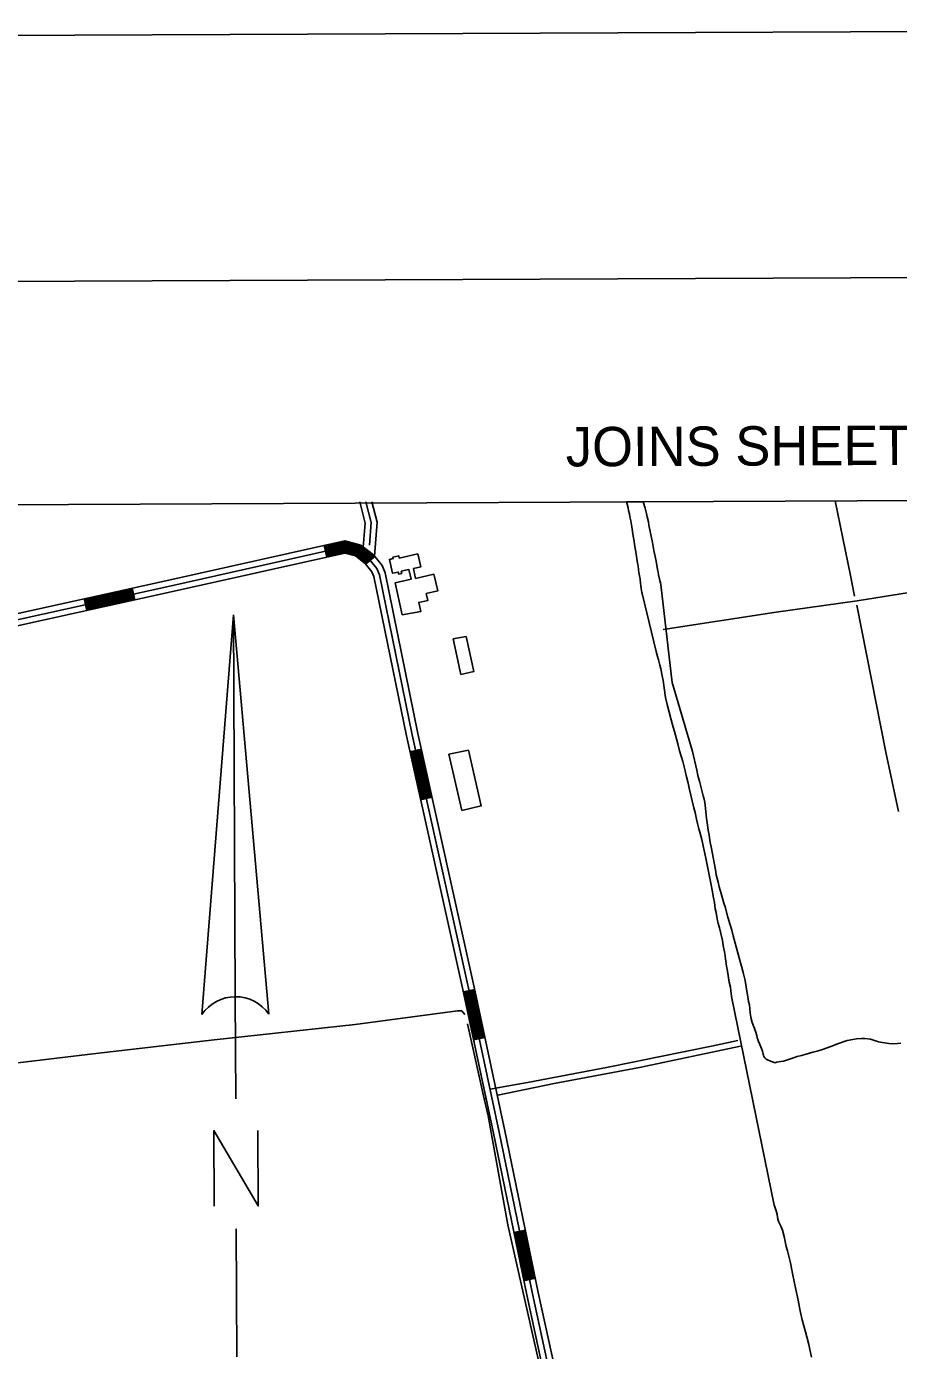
# Model space of a CAD drawing. Extents: x 3424494 to 3462436, y 522220 to 547718.
# Drawn here: x 3456706 to 3458923, y 543771 to 547135 of the extents above; entities that cross this region are included whole.
import ezdxf

# ---------------------------------------------------------------- set-up
doc = ezdxf.new("R2010")
doc.units = 0
for name, color, linetype in [('G-ANNO-NPLT', 7, 'Continuous'), ('V-ANNO-SYMB', 7, 'Continuous'), ('V-ANNO-TEXT', 7, 'Continuous'), ('V-BLDG-OTLN', 7, 'Continuous'), ('V-DTCH-CNTR', 7, 'Continuous'), ('V-GRID-FRAM', 7, 'Continuous'), ('V-ROAD-CNTR', 7, 'Continuous'), ('V-SITE-VEGE', 7, 'Continuous'), ('V-TOPO-SHOR', 7, 'Continuous')]:
    doc.layers.add(name, color=color, linetype=linetype)

msp = doc.modelspace()

# ---------------------------------------------------------------- linework, layer by layer
at = {"layer": 'G-ANNO-NPLT'}
msp.add_lwpolyline([(3425186.3, 522803.1), (3461852.6, 522968.4), (3461743.6, 547134.8), (3425077.3, 546969.5)], close=True, dxfattribs=at)
at = {"layer": 'V-ANNO-SYMB'}
for p, q in [((3457232.6, 545639.7), (3457152.2, 544624.3)), ((3457232.6, 545639.7), (3457322.2, 544625)), ((3457237, 544669.7), (3457232.6, 545639.7)), ((3457232.6, 545639.7), (3457322.2, 544625)), ((3457237, 544669.7), (3457232.6, 545639.7)), ((3457238.2, 544409.7), (3457237, 544669.7)), ((3457241.1, 543754.7), (3457239.6, 544079.7))]:
    msp.add_line(p, q, dxfattribs=at)
for points in [[(3427933.6, 523440.5), (3461016.5, 523589.7), (3460913.1, 546506), (3427830.3, 546356.9), (3427933.6, 523440.5)], [(3457183.4, 544137.4), (3457182.5, 544329.4), (3457295.4, 544137.9), (3457294.5, 544329.9)]]:
    msp.add_lwpolyline(points, dxfattribs=at)
for start, end in [(90.2583, 146.0529), (34.4638, 90.2583), (34.4638, 90.2472)]:
    msp.add_arc((3457237.4, 544566.9), 102.8, start, end, dxfattribs=at)
at = {"layer": 'V-BLDG-OTLN'}
for points in [[(3457661.4, 545639.6), (3457643.1, 545721), (3457684, 545730.3), (3457678.4, 545754.9), (3457659, 545750.5), (3457660.2, 545745.2), (3457652.3, 545743.4), (3457651.1, 545748.7), (3457636.6, 545745.4), (3457628.6, 545780.8), (3457638.6, 545783.1), (3457637.8, 545786.7), (3457652.6, 545790.1), (3457653.9, 545784), (3457700.8, 545794.7), (3457708.3, 545761.5), (3457689.8, 545757.3), (3457695.4, 545732.5), (3457742, 545743), (3457751.6, 545700.5), (3457722.5, 545693.9), (3457726.4, 545676.7), (3457703.4, 545671.4), (3457708.7, 545648.4)], [(3457823.9, 545584.8), (3457843.1, 545495.7), (3457810.5, 545488.6), (3457791.2, 545578.5)], [(3457829.6, 545296.1), (3457862.3, 545154.3), (3457812.9, 545143), (3457780, 545285.8)]]:
    msp.add_lwpolyline(points, close=True, dxfattribs=at)
at = {"layer": 'V-DTCH-CNTR'}
for points in [[(3458324.4, 545602.4), (3458611.5, 545647), (3458817.3, 545675.8), (3459230, 545741.9), (3459321.7, 545756.6), (3459657.1, 545812.5), (3460000.9, 545861.5), (3460200.9, 545894.6)], [(3458514, 544558.1), (3458447.3, 544544), (3458380.6, 544530.2), (3458313.9, 544516.6), (3458247.1, 544503.3), (3458180.3, 544490.1), (3458113.4, 544477.1), (3458046.5, 544464.4), (3457979.5, 544451.8), (3457912.6, 544439.5), (3457885.6, 544434.6)]]:
    msp.add_lwpolyline(points, dxfattribs=at)
at = {"layer": 'V-GRID-FRAM'}
msp.add_lwpolyline([(3428547.8, 545793.2), (3460200.7, 545935.9)], dxfattribs=at)
at = {"layer": 'V-ROAD-CNTR'}
for p, q in [((3457462.8, 545815.9), (3457469.3, 545786.6)), ((3457591.5, 545787.9), (3457568.2, 545769)), ((3456852.7, 545680.4), (3456859.2, 545651.1)), ((3456974.8, 545707.3), (3456981.2, 545678)), ((3457710.1, 545298.5), (3457680.8, 545292)), ((3457737.2, 545176.5), (3457707.9, 545170)), ((3457845.5, 544688.2), (3457816.2, 544682)), ((3457871.7, 544566), (3457842.3, 544559.7)), ((3457974.4, 544076.6), (3457945.1, 544070.5)), ((3457999.7, 543954.1), (3457970.3, 543948.1))]:
    msp.add_line(p, q, dxfattribs=at)
for points in [[(3456408.7, 545919), (3456433.5, 545801.4), (3456459.9, 545662.7), (3456474.1, 545632.8), (3456495.3, 545610.6), (3456539, 545593.8), (3456582.2, 545590), (3457081.9, 545700.2), (3457515.1, 545796.8), (3457542.2, 545789.4), (3457567.1, 545770.4), (3457584.1, 545749.5), (3457589.3, 545737.4), (3457671.8, 545332.2), (3457815, 544687.7), (3457893.1, 544322.5), (3457977.8, 543911.9), (3458020.4, 543715.5)], [(3456423.4, 545922.1), (3456448.2, 545804.4), (3456474.3, 545667.3), (3456486.6, 545641.4), (3456503.9, 545623.4), (3456542.4, 545608.6), (3456581.3, 545605.1), (3457078.6, 545714.8), (3457515.5, 545812.3), (3457549, 545803.1), (3457577.6, 545781.3), (3457597.1, 545757.3), (3457603.7, 545741.9), (3457686.5, 545335.3), (3457829.6, 544690.9), (3457907.8, 544325.6), (3457992.4, 543915), (3458035.1, 543718.6)], [(3456438.1, 545925.2), (3456463, 545807.3), (3456488.7, 545672), (3456499.1, 545650), (3456512.4, 545636.2), (3456545.8, 545623.3), (3456580.3, 545620.3), (3457075.4, 545729.5), (3457515.8, 545827.7), (3457555.7, 545816.8), (3457588.1, 545792.1), (3457610, 545765.2), (3457618.1, 545746.4), (3457701.2, 545338.4), (3457844.3, 544694.1), (3457922.4, 544328.7), (3458007.1, 543918.1), (3458049.8, 543721.7)], [(3457553.3, 545927.2), (3457567.3, 545872.8), (3457562.3, 545811.8)], [(3457577.8, 545817.3), (3457582.5, 545874.1), (3457568.8, 545927.2)], [(3457584.3, 545927.3), (3457597.6, 545875.4), (3457590.5, 545789.2)], [(3457463.4, 545813), (3457515.8, 545824.6), (3457554.4, 545814.1), (3457586, 545790), (3457589.2, 545786)], [(3457464.1, 545810), (3457515.7, 545821.5), (3457553, 545811.3), (3457583.9, 545787.8), (3457586.9, 545784.1)], [(3457464.7, 545807.1), (3457515.6, 545818.4), (3457551.7, 545808.6), (3457581.8, 545785.6), (3457584.6, 545782.2)], [(3457465.4, 545804.2), (3457515.5, 545815.3), (3457550.3, 545805.9), (3457579.7, 545783.5), (3457582.2, 545780.4)], [(3457466.1, 545801.2), (3457515.5, 545812.3), (3457549, 545803.1), (3457577.6, 545781.3), (3457579.9, 545778.5)], [(3457466.7, 545798.3), (3457515.4, 545809.2), (3457547.6, 545800.4), (3457575.5, 545779.1), (3457577.6, 545776.6)], [(3457467.4, 545795.4), (3457515.3, 545806.1), (3457546.2, 545797.6), (3457573.4, 545777), (3457575.2, 545774.7)], [(3457468, 545792.5), (3457515.3, 545803), (3457544.9, 545794.9), (3457571.3, 545774.8), (3457572.9, 545772.8)], [(3457468.7, 545789.5), (3457515.2, 545799.9), (3457543.5, 545792.2), (3457569.2, 545772.6), (3457570.6, 545770.9)], [(3456853.3, 545677.4), (3456975.4, 545704.4)], [(3456854, 545674.5), (3456976.1, 545701.4)], [(3456854.6, 545671.6), (3456976.7, 545698.5)], [(3456855.3, 545668.7), (3456977.3, 545695.6)], [(3456855.9, 545665.7), (3456978, 545692.6)], [(3456856.6, 545662.8), (3456978.6, 545689.7)], [(3456857.2, 545659.9), (3456979.3, 545686.8)], [(3456857.9, 545656.9), (3456979.9, 545683.9)], [(3456858.5, 545654), (3456980.6, 545680.9)], [(3457683.7, 545292.6), (3457710.8, 545170.6)], [(3457686.6, 545293.3), (3457713.7, 545171.3)], [(3457689.6, 545293.9), (3457716.7, 545171.9)], [(3457692.5, 545294.6), (3457719.6, 545172.6)], [(3457695.4, 545295.2), (3457722.5, 545173.2)], [(3457698.3, 545295.9), (3457725.4, 545173.9)], [(3457701.3, 545296.5), (3457728.4, 545174.5)], [(3457704.2, 545297.2), (3457731.3, 545175.2)], [(3457707.1, 545297.8), (3457734.2, 545175.8)], [(3457819.1, 544682.6), (3457845.3, 544560.4)], [(3457822.1, 544683.2), (3457848.2, 544561)], [(3457825, 544683.8), (3457851.1, 544561.6)], [(3457827.9, 544684.5), (3457854.1, 544562.2)], [(3457830.9, 544685.1), (3457857, 544562.9)], [(3457833.8, 544685.7), (3457859.9, 544563.5)], [(3457836.7, 544686.3), (3457862.9, 544564.1)], [(3457839.7, 544687), (3457865.8, 544564.7)], [(3457842.6, 544687.6), (3457868.7, 544565.4)], [(3457948, 544071.1), (3457973.2, 543948.7)], [(3457950.9, 544071.7), (3457976.2, 543949.3)], [(3457953.9, 544072.3), (3457979.1, 543949.9)], [(3457956.8, 544072.9), (3457982.1, 543950.5)], [(3457959.8, 544073.5), (3457985, 543951.1)], [(3457962.7, 544074.1), (3457987.9, 543951.7)], [(3457965.6, 544074.7), (3457990.9, 543952.3)], [(3457968.6, 544075.4), (3457993.8, 543952.9)], [(3457971.5, 544076), (3457996.8, 543953.5)]]:
    msp.add_lwpolyline(points, dxfattribs=at)
at = {"layer": 'V-SITE-VEGE'}
for p, q in [((3458231.7, 545927), (3458273.9, 545927.2)), ((3458235.4, 545911.4), (3458231.7, 545927)), ((3458273.9, 545927.2), (3458278.5, 545911.3)), ((3458236.6, 545905.1), (3458235.4, 545911.4)), ((3458238.8, 545896.3), (3458236.6, 545905.1)), ((3458240.1, 545889.2), (3458238.8, 545896.3)), ((3458242.4, 545878.7), (3458240.1, 545889.2)), ((3458244.7, 545863.6), (3458242.4, 545878.7)), ((3458278.5, 545911.3), (3458281.8, 545897.5)), ((3458281.8, 545897.5), (3458284.1, 545888.5)), ((3458284.1, 545888.5), (3458286.9, 545876.1)), ((3458245.9, 545857.6), (3458244.7, 545863.6)), ((3458248.5, 545839.4), (3458245.9, 545857.6)), ((3458286.9, 545876.1), (3458288.4, 545867.8)), ((3458288.4, 545867.8), (3458297.5, 545823.3)), ((3458250.6, 545827), (3458248.5, 545839.4)), ((3458251.9, 545818.2), (3458250.6, 545827)), ((3458254.2, 545804.2), (3458251.9, 545818.2)), ((3458297.5, 545823.3), (3458301, 545803.2)), ((3458255, 545800), (3458254.2, 545804.2)), ((3458259.5, 545771.3), (3458255, 545800)), ((3458301, 545803.2), (3458302.7, 545795.5)), ((3458302.7, 545795.5), (3458306.6, 545776.2)), ((3458260.7, 545764.8), (3458259.5, 545771.3)), ((3458262.2, 545754.6), (3458260.7, 545764.8)), ((3458262.9, 545747.7), (3458262.2, 545754.6)), ((3458265.8, 545730.7), (3458262.9, 545747.7)), ((3458306.6, 545776.2), (3458310.2, 545755.5)), ((3458310.2, 545755.5), (3458311.8, 545748.1)), ((3458311.8, 545748.1), (3458312.7, 545741.7)), ((3458267.1, 545719.8), (3458265.8, 545730.7)), ((3458267.4, 545714.2), (3458267.1, 545719.8)), ((3458269, 545707.1), (3458267.4, 545714.2)), ((3458312.7, 545741.7), (3458316.5, 545727.2)), ((3458316.5, 545727.2), (3458317.8, 545721.5)), ((3458317.8, 545721.5), (3458318.6, 545716.9)), ((3458318.6, 545716.9), (3458345.1, 545488.9)), ((3458270.7, 545696.4), (3458269, 545707.1)), ((3458271.3, 545694.3), (3458270.7, 545696.4)), ((3458307.1, 545546.4), (3458271.3, 545694.3)), ((3458310.3, 545534.1), (3458307.1, 545546.4)), ((3458312.4, 545525.5), (3458310.3, 545534.1)), ((3458316.1, 545512.4), (3458312.4, 545525.5)), ((3458318.5, 545502.3), (3458316.1, 545512.4)), ((3458322, 545485.2), (3458318.5, 545502.3)), ((3458324.3, 545472.7), (3458322, 545485.2)), ((3458345.1, 545488.9), (3458347.3, 545467.6)), ((3458327.2, 545454.6), (3458324.3, 545472.7)), ((3458330.9, 545430.1), (3458327.2, 545454.6)), ((3458347.3, 545467.6), (3458399.4, 545292.9)), ((3458334.8, 545412.2), (3458330.9, 545430.1)), ((3458344.8, 545372.8), (3458334.8, 545412.2)), ((3458349.7, 545354.9), (3458344.8, 545372.8)), ((3458353.1, 545343.2), (3458349.7, 545354.9)), ((3458358.4, 545324.5), (3458353.1, 545343.2)), ((3458361.5, 545312.2), (3458358.4, 545324.5)), ((3458366.2, 545294.5), (3458361.5, 545312.2)), ((3458374.3, 545266.9), (3458366.2, 545294.5)), ((3458399.4, 545292.9), (3458409.9, 545245.2)), ((3458380.2, 545243.7), (3458374.3, 545266.9)), ((3458383.1, 545231.5), (3458380.2, 545243.7)), ((3458409.9, 545245.2), (3458412.8, 545231.7)), ((3458387.8, 545212.4), (3458383.1, 545231.5)), ((3458390.7, 545199.5), (3458387.8, 545212.4)), ((3458412.8, 545231.7), (3458417.4, 545214)), ((3458417.4, 545214), (3458420.7, 545203.3)), ((3458402.9, 545149.8), (3458390.7, 545199.5)), ((3458420.7, 545203.3), (3458426.4, 545180.2)), ((3458426.4, 545180.2), (3458428.5, 545171.5)), ((3458405.8, 545137.7), (3458402.9, 545149.8)), ((3458428.5, 545171.5), (3458430.1, 545162.9)), ((3458430.1, 545162.9), (3458432.2, 545148.8)), ((3458432.2, 545148.8), (3458433.4, 545139.3)), ((3458433.4, 545139.3), (3458434.9, 545123.5)), ((3458409.3, 545120.4), (3458405.8, 545137.7)), ((3458411.7, 545110.1), (3458409.3, 545120.4)), ((3458415.2, 545096.5), (3458411.7, 545110.1)), ((3458434.9, 545123.5), (3458436.2, 545111.4)), ((3458436.2, 545111.4), (3458438.7, 545093.1)), ((3458417.8, 545087.4), (3458415.2, 545096.5)), ((3458422.5, 545069.3), (3458417.8, 545087.4)), ((3458438.7, 545093.1), (3458441.2, 545080.2)), ((3458441.2, 545080.2), (3458444.3, 545061.7)), ((3458426, 545053), (3458422.5, 545069.3)), ((3458428.9, 545041.5), (3458426, 545053)), ((3458433, 545021.8), (3458428.9, 545041.5)), ((3458444.3, 545061.7), (3458446.3, 545050.4)), ((3458446.3, 545050.4), (3458457.4, 544991.9)), ((3458435.8, 545008.7), (3458433, 545021.8)), ((3458439.9, 544988), (3458435.8, 545008.7)), ((3458442.4, 544974.9), (3458439.9, 544988)), ((3458446.9, 544954), (3458442.4, 544974.9)), ((3458457.4, 544991.9), (3458459.7, 544979)), ((3458459.7, 544979), (3458464, 544960.9)), ((3458448.8, 544940.3), (3458446.9, 544954)), ((3458452.7, 544920.6), (3458448.8, 544940.3)), ((3458464, 544960.9), (3458467.3, 544948.7)), ((3458467.3, 544948.7), (3458472.3, 544932.1)), ((3458454.8, 544908.9), (3458452.7, 544920.6)), ((3458457, 544892.9), (3458454.8, 544908.9)), ((3458472.3, 544932.1), (3458479.1, 544907.6)), ((3458479.1, 544907.6), (3458481.9, 544898.3)), ((3458458.9, 544883.2), (3458457, 544892.9)), ((3458462.2, 544867.1), (3458458.9, 544883.2)), ((3458481.9, 544898.3), (3458489, 544871.6)), ((3458489, 544871.6), (3458494.9, 544852.2)), ((3458464.6, 544856), (3458462.2, 544867.1)), ((3458467.5, 544844.4), (3458464.6, 544856)), ((3458475.1, 544812.8), (3458467.5, 544844.4)), ((3458494.9, 544852.2), (3458498.8, 544838.4)), ((3458498.8, 544838.4), (3458502.3, 544824.5)), ((3458477.5, 544799.7), (3458475.1, 544812.8)), ((3458502.3, 544824.5), (3458515.5, 544777.6)), ((3458481, 544779.4), (3458477.5, 544799.7)), ((3458483.1, 544765.9), (3458481, 544779.4)), ((3458515.5, 544777.6), (3458520.6, 544758.8)), ((3458485.8, 544746.8), (3458483.1, 544765.9)), ((3458487.7, 544734.5), (3458485.8, 544746.8)), ((3458492.6, 544706.8), (3458487.7, 544734.5)), ((3458520.6, 544758.8), (3458523.8, 544747.2)), ((3458523.8, 544747.2), (3458527.9, 544731.3)), ((3458495.5, 544693.7), (3458492.6, 544706.8)), ((3458527.9, 544731.3), (3458530.4, 544721.2)), ((3458530.4, 544721.2), (3458532.6, 544711)), ((3458532.6, 544711), (3458537.8, 544679)), ((3458496.9, 544685.5), (3458495.5, 544693.7)), ((3458498.4, 544670.2), (3458496.9, 544685.5)), ((3458606.4, 544139.7), (3458498.4, 544670.2)), ((3458537.8, 544679), (3458539.6, 544669.7)), ((3458539.6, 544669.7), (3458541.9, 544657.4)), ((3458541.9, 544657.4), (3458543.8, 544648.6)), ((3458543.8, 544648.6), (3458545.2, 544638.9)), ((3458545.2, 544638.9), (3458546.1, 544628.9)), ((3458546.1, 544628.9), (3458546.3, 544623.1)), ((3458546.3, 544623.1), (3458548.2, 544613.6)), ((3458548.2, 544613.6), (3458550.8, 544604.3)), ((3458550.8, 544604.3), (3458559.5, 544582.2)), ((3458559.5, 544582.2), (3458563, 544571.3)), ((3458563, 544571.3), (3458563.6, 544565.5)), ((3458563.6, 544565.5), (3458566.2, 544558.2)), ((3458566.2, 544558.2), (3458567, 544555.4)), ((3458567, 544555.4), (3458569.9, 544548.2)), ((3458569.9, 544548.2), (3458574.5, 544537.7)), ((3458574.5, 544537.7), (3458576.7, 544530.9)), ((3458715.9, 544531.6), (3458732, 544536.7)), ((3458732, 544536.7), (3458757.2, 544545.6)), ((3458757.2, 544545.6), (3458767.9, 544549.6)), ((3458767.9, 544549.6), (3458792.6, 544558)), ((3458792.6, 544558), (3458806.9, 544561.2)), ((3458806.9, 544561.2), (3458815.8, 544562.9)), ((3458815.8, 544562.9), (3458828.6, 544563.8)), ((3458828.6, 544563.8), (3458837.5, 544563.6)), ((3458837.5, 544563.6), (3458851.7, 544561.7)), ((3458851.7, 544561.7), (3458856.7, 544560.3)), ((3458856.7, 544560.3), (3458872, 544555.3)), ((3458872, 544555.3), (3458882.4, 544552.9)), ((3458882.4, 544552.9), (3458897.9, 544550.3)), ((3458897.9, 544550.3), (3458907.3, 544549.9)), ((3458907.3, 544549.9), (3458920.2, 544550.6)), ((3458920.2, 544550.6), (3458928.4, 544551.8)), ((3458576.7, 544530.9), (3458578.6, 544523.8)), ((3458578.6, 544523.8), (3458579.2, 544520.8)), ((3458579.2, 544520.8), (3458580.8, 544517.4)), ((3458580.8, 544517.4), (3458582.8, 544514.7)), ((3458582.8, 544514.7), (3458586.8, 544511.1)), ((3458586.8, 544511.1), (3458589.6, 544509.1)), ((3458589.6, 544509.1), (3458597.8, 544505.6)), ((3458597.8, 544505.6), (3458604.8, 544503.1)), ((3458604.8, 544503.1), (3458608.2, 544501.3)), ((3458608.2, 544501.3), (3458610.8, 544502.5)), ((3458610.8, 544502.5), (3458612.7, 544503.1)), ((3458612.7, 544503.1), (3458623.5, 544504.6)), ((3458623.5, 544504.6), (3458630.4, 544506.2)), ((3458630.4, 544506.2), (3458655.7, 544514.5)), ((3458655.7, 544514.5), (3458665.2, 544517.8)), ((3458665.2, 544517.8), (3458676.5, 544520.6)), ((3458676.5, 544520.6), (3458688.1, 544523.9)), ((3458688.1, 544523.9), (3458705, 544528.4)), ((3458705, 544528.4), (3458715.9, 544531.6)), ((3458608.4, 544135.6), (3458606.4, 544139.7)), ((3458611.9, 544125.8), (3458608.4, 544135.6)), ((3458614.1, 544116.5), (3458611.9, 544125.8)), ((3458616.4, 544104.2), (3458614.1, 544116.5)), ((3458619, 544096.6), (3458616.4, 544104.2)), ((3458624.5, 544084.5), (3458619, 544096.6)), ((3458627.9, 544076), (3458624.5, 544084.5)), ((3458632.2, 544060.3), (3458627.9, 544076)), ((3458636.9, 544034.8), (3458632.2, 544060.3)), ((3458640.4, 544024.1), (3458636.9, 544034.8)), ((3458647.9, 543993.5), (3458640.4, 544024.1)), ((3458650.4, 543979.9), (3458647.9, 543993.5)), ((3458653.3, 543966.4), (3458650.4, 543979.9)), ((3458657.4, 543946.1), (3458653.3, 543966.4)), ((3458662.1, 543925.9), (3458657.4, 543946.1)), ((3458667.8, 543898.8), (3458662.1, 543925.9)), ((3458671.3, 543879.7), (3458667.8, 543898.8)), ((3458674, 543867.6), (3458671.3, 543879.7)), ((3458677.7, 543848.9), (3458674, 543867.6)), ((3458686.1, 543817.9), (3458677.7, 543848.9)), ((3458689.9, 543805), (3458686.1, 543817.9)), ((3458694.8, 543785.7), (3458689.9, 543805)), ((3458697.3, 543773), (3458694.8, 543785.7)), ((3458702, 543753.5), (3458697.3, 543773))]:
    msp.add_line(p, q, dxfattribs=at)
at = {"layer": 'V-TOPO-SHOR'}
msp.add_line((3457875.3, 544412.2), (3457869.9, 544410), dxfattribs=at)
for points in [[(3458761.9, 545929.4), (3458801, 545740.2), (3458810.6, 545687.5)], [(3458817, 545664.3), (3458890.7, 545290.7), (3458922.6, 545140.3)], [(3456458.7, 544480.9), (3456494.4, 544476.5), (3456584.4, 544489.5), (3456882.2, 544525.4), (3457183, 544559.9), (3457541.3, 544599.4), (3457801.9, 544633.6), (3457812.7, 544633.6), (3457820.5, 544624.4)], [(3457826.9, 544601.1), (3457869.9, 544410), (3457879.6, 544367.1), (3457929.4, 544089.6), (3458007.6, 543745.5)], [(3458521, 544544.2), (3458264.4, 544489.8), (3458047.4, 544448.9), (3457904, 544419.3)]]:
    msp.add_lwpolyline(points, dxfattribs=at)

# ---------------------------------------------------------------- texts
at = {"layer": 'V-ANNO-TEXT'}
msp.add_text('JOINS SHEET 41', height=100, rotation=0.2583, dxfattribs=at).set_placement((3458077.2, 546016.9))

doc.saveas('drawing.dxf')
